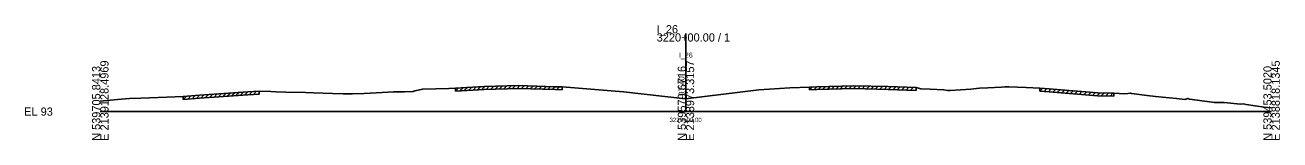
# Model space of a CAD drawing. Extents: x -13101 to 4803, y -924 to 22390.
# Drawn here: x 1974.3 to 2402.8, y 9990.3 to 10029.6 of the extents above; entities that cross this region are included whole.
import ezdxf

# ---------------------------------------------------------------- set-up
doc = ezdxf.new("R2010")
doc.units = 0
for name, color, linetype in [('RD_GPK_XS_Cell', 7, 'Continuous'), ('RD_XS_ExGround', 7, 'Continuous'), ('RD_XS_ExPaveRet', 7, 'Continuous'), ('RD_XS_TX_Baseline', 7, 'Continuous'), ('RD_XS_TX_Elev_EX', 7, 'Continuous'), ('RD_XS_TX_Station', 7, 'Continuous')]:
    doc.layers.add(name, color=color, linetype=linetype)

msp = doc.modelspace()

# ---------------------------------------------------------------- linework, layer by layer
at = {"layer": 'RD_GPK_XS_Cell'}
for p, q in [((2200, 10000), (2200, 10026.75)), ((2000, 10000), (2200, 10000)), ((2200, 10000), (2400, 10000))]:
    msp.add_line(p, q, dxfattribs=at)
at = {"layer": 'RD_XS_ExGround'}
msp.add_lwpolyline([(2000, 10003.54), (2005.85, 10004.1), (2010, 10004.46), (2013.81, 10004.58), (2022.72, 10004.98), (2028.33, 10005.18), (2033.88, 10005.61), (2050.43, 10006.75), (2054.24, 10006.99), (2058.22, 10006.86), (2060.05, 10006.8), (2063.38, 10006.68), (2070.06, 10006.52), (2072.82, 10006.42), (2079.26, 10006.18), (2082.95, 10006.12), (2086.08, 10006.09), (2090.08, 10006.18), (2098.26, 10006.65), (2100.09, 10006.76), (2103.83, 10006.81), (2106.85, 10006.88), (2107.46, 10007.11), (2110.1, 10007.71), (2119.06, 10007.93), (2121.31, 10008.02), (2131.03, 10008.58), (2142.76, 10008.92), (2155.34, 10008.5), (2157.69, 10008.44), (2178.66, 10006.81), (2199.84, 10004.38), (2224.87, 10007.41), (2235.52, 10008.09), (2242.17, 10008.39), (2244.67, 10008.5), (2257.38, 10008.86), (2269.09, 10008.55), (2278.63, 10008.21), (2280.26, 10007.83), (2283.35, 10007.68), (2288.09, 10007.42), (2289.32, 10007.26), (2290.27, 10007.24), (2297.3, 10007.72), (2300.28, 10008.02), (2303.08, 10008.12), (2307.8, 10008.33), (2308.9, 10008.41), (2310.29, 10008.45), (2316.15, 10008.24), (2320.82, 10007.99), (2324.05, 10007.79), (2340.55, 10006.36), (2346.11, 10006.27), (2349.8, 10006.07), (2350.95, 10006.15), (2351.8, 10006.25), (2352.16, 10006.2), (2357.55, 10005.54), (2360.37, 10005.2), (2367.57, 10004.46), (2370.41, 10004.18), (2371.4, 10004.48), (2371.94, 10004.29), (2379.68, 10003.23), (2380.35, 10003.13), (2383.8, 10003.13), (2389.35, 10002.54), (2390.39, 10002.6), (2391.37, 10002.41), (2397.49, 10001.55), (2400, 10001.23)], dxfattribs=at)
at = {"layer": 'RD_XS_ExPaveRet'}
for p, q in [((2043.33, 10005.26), (2044.4, 10006.34)), ((2044.83, 10005.37), (2045.9, 10006.44)), ((2046.33, 10005.47), (2047.4, 10006.54)), ((2047.83, 10005.57), (2048.9, 10006.65)), ((2049.33, 10005.68), (2050.4, 10006.75)), ((2050.83, 10005.78), (2051.89, 10006.84)), ((2052.33, 10005.87), (2053.39, 10006.93)), ((2054.24, 10006.99), (2054.24, 10005.99)), ((2121.31, 10007.02), (2122.37, 10008.08)), ((2121.31, 10007.02), (2121.31, 10008.02)), ((2121.31, 10007.02), (2131.03, 10007.58)), ((2122.81, 10007.11), (2123.87, 10008.17)), ((2124.31, 10007.2), (2125.37, 10008.26)), ((2125.81, 10007.28), (2126.87, 10008.34)), ((2127.31, 10007.37), (2128.37, 10008.43)), ((2128.81, 10007.46), (2129.87, 10008.52)), ((2130.31, 10007.54), (2131.36, 10008.59)), ((2131.03, 10007.58), (2142.76, 10007.92)), ((2131.81, 10007.61), (2132.84, 10008.64)), ((2133.31, 10007.65), (2134.34, 10008.68)), ((2134.81, 10007.69), (2135.84, 10008.72)), ((2136.31, 10007.73), (2137.34, 10008.76)), ((2137.81, 10007.78), (2138.84, 10008.8)), ((2139.31, 10007.82), (2140.34, 10008.85)), ((2140.81, 10007.86), (2141.84, 10008.89)), ((2142.31, 10007.9), (2143.3, 10008.9)), ((2142.76, 10007.92), (2155.34, 10007.5)), ((2143.81, 10007.88), (2144.77, 10008.85)), ((2145.31, 10007.83), (2146.27, 10008.8)), ((2146.81, 10007.78), (2147.77, 10008.75)), ((2148.31, 10007.73), (2149.27, 10008.7)), ((2149.81, 10007.68), (2150.77, 10008.65)), ((2151.31, 10007.63), (2152.27, 10008.6)), ((2152.81, 10007.59), (2153.77, 10008.55)), ((2154.31, 10007.54), (2155.27, 10008.5)), ((2155.34, 10007.5), (2157.69, 10007.44)), ((2155.81, 10007.49), (2156.78, 10008.46)), ((2157.69, 10008.44), (2157.69, 10007.44)), ((2242.17, 10007.39), (2243.21, 10008.44)), ((2242.17, 10007.39), (2242.17, 10008.39)), ((2242.17, 10007.39), (2244.67, 10007.5)), ((2243.67, 10007.46), (2244.71, 10008.5)), ((2244.67, 10007.5), (2257.38, 10007.86)), ((2245.17, 10007.51), (2246.2, 10008.54)), ((2246.67, 10007.55), (2247.7, 10008.58)), ((2248.17, 10007.6), (2249.2, 10008.63)), ((2249.67, 10007.64), (2250.7, 10008.67)), ((2251.17, 10007.68), (2252.2, 10008.71)), ((2252.67, 10007.73), (2253.7, 10008.76)), ((2254.17, 10007.77), (2255.2, 10008.8)), ((2255.67, 10007.81), (2256.7, 10008.84)), ((2257.17, 10007.86), (2258.15, 10008.84)), ((2257.38, 10007.86), (2269.09, 10007.55)), ((2258.67, 10007.83), (2259.64, 10008.8)), ((2260.17, 10007.79), (2261.14, 10008.76)), ((2261.67, 10007.75), (2262.64, 10008.72)), ((2263.17, 10007.71), (2264.14, 10008.68)), ((2264.67, 10007.67), (2265.64, 10008.64)), ((2266.17, 10007.63), (2267.14, 10008.6)), ((2267.67, 10007.59), (2268.64, 10008.56)), ((2269.09, 10007.55), (2278.63, 10007.21)), ((2269.17, 10007.54), (2270.13, 10008.51)), ((2270.67, 10007.49), (2271.63, 10008.46)), ((2272.17, 10007.44), (2273.13, 10008.41)), ((2273.67, 10007.39), (2274.63, 10008.35)), ((2275.17, 10007.33), (2276.13, 10008.3)), ((2276.67, 10007.28), (2277.63, 10008.25)), ((2278.63, 10008.21), (2278.63, 10007.21)), ((2320.82, 10006.99), (2320.82, 10007.99)), ((2320.82, 10006.99), (2321.76, 10007.94)), ((2320.82, 10006.99), (2324.05, 10006.79)), ((2322.32, 10006.9), (2323.26, 10007.84)), ((2323.82, 10006.81), (2324.75, 10007.73)), ((2324.05, 10006.79), (2340.55, 10005.36)), ((2325.32, 10006.68), (2326.24, 10007.6)), ((2326.82, 10006.55), (2327.74, 10007.47)), ((2328.32, 10006.42), (2329.24, 10007.34)), ((2329.82, 10006.29), (2330.74, 10007.21)), ((2331.32, 10006.16), (2332.24, 10007.08)), ((2332.82, 10006.03), (2333.74, 10006.95)), ((2334.32, 10005.9), (2335.24, 10006.82)), ((2335.82, 10005.77), (2336.74, 10006.69)), ((2337.32, 10005.64), (2338.24, 10006.56)), ((2338.82, 10005.51), (2339.74, 10006.43)), ((2340.32, 10005.38), (2341.29, 10006.35)), ((2341.82, 10005.34), (2342.81, 10006.32)), ((2343.32, 10005.31), (2344.31, 10006.3)), ((2344.82, 10005.29), (2345.81, 10006.28)), ((2346.11, 10006.27), (2346.11, 10005.27)), ((2028.33, 10004.18), (2029.41, 10005.26)), ((2028.33, 10004.18), (2028.33, 10005.18)), ((2028.33, 10004.18), (2033.88, 10004.61)), ((2029.83, 10004.3), (2030.91, 10005.38)), ((2031.33, 10004.41), (2032.41, 10005.49)), ((2032.83, 10004.53), (2033.91, 10005.61)), ((2033.88, 10004.61), (2050.43, 10005.75)), ((2034.33, 10004.64), (2035.4, 10005.71)), ((2035.83, 10004.74), (2036.9, 10005.82)), ((2037.33, 10004.84), (2038.4, 10005.92)), ((2038.83, 10004.95), (2039.9, 10006.02)), ((2040.33, 10005.05), (2041.4, 10006.13)), ((2041.83, 10005.16), (2042.9, 10006.23)), ((2050.43, 10005.75), (2054.24, 10005.99)), ((2340.55, 10005.36), (2346.11, 10005.27))]:
    msp.add_line(p, q, dxfattribs=at)

# ---------------------------------------------------------------- texts
at = {"layer": 'RD_GPK_XS_Cell'}
for s, p in [('I_26', (2190, 10026.75)), ('3220+00.00 / 1', (2190, 10023.95)), ('EL 93', (1974, 9998.6))]:
    msp.add_text(s, height=2.8, dxfattribs=at).set_placement(p)
for s, p in [('N 539705.8413', (2000, 9990)), ('E 2139128.4969', (2002.8, 9990)), ('N 539579.6716', (2200, 9990)), ('E 2138973.3157', (2202.8, 9990)), ('N 539453.5020', (2400, 9990)), ('E 2138818.1345', (2402.8, 9990))]:
    msp.add_text(s, height=2.8, rotation=90, dxfattribs=at).set_placement(p)
at = {"layer": 'RD_XS_TX_Baseline'}
msp.add_text('I_26', height=1.75, dxfattribs=at).set_placement((2197.6, 10018.4))
at = {"layer": 'RD_XS_TX_Elev_EX'}
msp.add_text('97.40', height=2, rotation=90, dxfattribs=at).set_placement((2199.5, 10005.4))
at = {"layer": 'RD_XS_TX_Station'}
msp.add_text('3220+00.00', height=1.5, dxfattribs=at).set_placement((2194.38, 9996.4))

doc.saveas('drawing.dxf')
